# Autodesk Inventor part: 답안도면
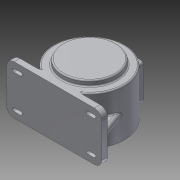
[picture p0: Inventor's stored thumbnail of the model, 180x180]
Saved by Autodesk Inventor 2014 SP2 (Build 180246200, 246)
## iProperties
Created: 2015-06
Part Number: 답안도면
Material: 알루미늄 6061
Document SubType Name: Sheet Metal
Designer: 201-01
Mass: 3440.74 g
Surface Area: 2277.39 cm^2
Volume: 1269.65 cm^3
Density: 2.71 g/cm^3
Sheet Metal Rule: Default_mm
Appearance: 알루미늄 - 평지
Author: 201-01
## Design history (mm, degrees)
sketch "스케치1"
  geometry: L1 (-97, 59)-(97, 59); L2 (115, 41)-(115, -41); L3 (97, -59)-(-97, -59); L4 (-115, -41)-(-115, 41); A1 r 18 centre (97, -41) between (97, -59) and (115, -41); A2 r 18 centre (97, 41) between (115, 41) and (97, 59); A3 r 18 centre (-97, 41) between (-97, 59) and (-115, 41); A4 r 18 centre (-97, -41) between (-115, -41) and (-97, -59); 4 further points
  constraints: 8 end point, 8 point on circle, 8 tangent, 6 point on line, 4 centre point, 3 equal radius, 2 parallel, 1 horizontal, 1 perpendicular
  dimensions: "d0" = 230 distance of point (115, -59) point (-115, -59); "d1" = 118 distance of point (-115, -59) point (-115, 59); "d2" = 115 horizontal distance of point (0, 0) point (-115, 59); "d4" = 59 vertical distance of point (0, 0) point (115, -59); "d5" = 18 radius of A1
extrude "돌출1" join sketch "스케치1" distance "d6" = 14; taper "d7" = 0 deg
sketch "스케치2"
  geometry: L1 (-115, 41)-(-115, -41) reference; L2 (-97, -59)-(97, -59) reference; L3 (115, -41)-(115, 41) reference; L4 (97, 59)-(-97, 59) reference; L5 (0, 59)-(0, 41); L6 (0, 41)-(97, 41); L7 (97, 41)-(81, 41); L8 (81, 50)-(97, 50); L9 (81, 32)-(97, 32); L10 (-115, 0)-(115, 0); L11 (81, -32)-(97, -32); L12 (81, -50)-(97, -50); L13 (-81, 32)-(-97, 32); L14 (-81, 50)-(-97, 50); L15 (-81, -32)-(-97, -32); L16 (-81, -50)-(-97, -50); A1 r 18 centre (-97, -41) between (-115, -41) and (-97, -59) reference; A2 r 18 centre (97, -41) between (97, -59) and (115, -41) reference; A3 r 18 centre (97, 41) between (115, 41) and (97, 59) reference; A4 r 18 centre (-97, 41) between (-97, 59) and (-115, 41) reference; A5 r 9 centre (97, 41) between (97, 32) and (97, 50); A6 r 9 centre (81, 41) between (81, 50) and (81, 32); A7 r 9 centre (97, -41) between (97, -50) and (97, -32); A8 r 9 centre (81, -41) between (81, -32) and (81, -50); A9 r 9 centre (-97, 41) between (-97, 50) and (-97, 32); A10 r 9 centre (-81, 41) between (-81, 32) and (-81, 50); A11 r 9 centre (-97, -41) between (-97, -32) and (-97, -50); A12 r 9 centre (-81, -41) between (-81, -50) and (-81, -32); 2 further points
  constraints: 24 end point, 19 symmetric about line, 16 point on circle, 8 centre point, 3 midpoint, 2 coincident, 2 tangent, 1 parallel, 1 perpendicular, 1 point on line, 6 other
  dimensions: "d9" = 18 distance of L5.start L5.end; "d11" = 16 distance of L6.end L7.end
extrude "돌출2" join sketch "스케치2" distance "d22" = 3; taper "d23" = 0 deg
sketch "스케치3"
  geometry: L1 (-97, 32)-(-81, 32) reference; L2 (-81, 50)-(-97, 50) reference; L3 (-97, 45)-(-81, 45); L4 (-81, 37)-(-97, 37); L5 (0, 0)-(0, 37); L6 (0, 0)-(-32.171, 0); L7 (97, 45)-(81, 45); L8 (81, 37)-(97, 37); L9 (-97, -45)-(-81, -45); L10 (-81, -37)-(-97, -37); L11 (97, -45)-(81, -45); L12 (81, -37)-(97, -37); A1 r 9 centre (-81, 41) between (-81, 32) and (-81, 50) reference; A2 r 9 centre (-97, 41) between (-97, 50) and (-97, 32) reference; A3 r 4 centre (-81, 41) between (-81, 37) and (-81, 45); A4 r 4 centre (-97, 41) between (-97, 45) and (-97, 37); A5 r 4 centre (81, 41) between (81, 45) and (81, 37); A6 r 4 centre (97, 41) between (97, 37) and (97, 45); A7 r 4 centre (-81, -41) between (-81, -45) and (-81, -37); A8 r 4 centre (-97, -41) between (-97, -37) and (-97, -45); A9 r 4 centre (81, -41) between (81, -37) and (81, -45); A10 r 4 centre (97, -41) between (97, -45) and (97, -37)
  constraints: 20 end point, 18 symmetric about line, 16 point on circle, 8 centre point, 2 perpendicular, 9 other
  dimensions: "d24" = 8 distance between parallel lines of L4 L3
extrude "돌출3" cut sketch "스케치3" stored distance "d25" = 3; taper "d26" = 0 deg
fillet "모깎기1" dims "d27" = 4
sketch "스케치5"
  geometry: L1 (0, 0)-(0, 85); C1 r 85 at (0, 85)
  constraints: 2 end point, 1 centre point, 1 coincident, 1 vertical
  dimensions: "d28" = 85 distance of L1.start L1.end; "d29" = 170 diameter of C1
extrude "돌출4" join sketch "스케치5" stored distance "d30" = 118; taper "d31" = 0 deg
sketch "스케치6"
  geometry: L1 (-97, 0)-(97, 0) reference; L2 (97, 0)-(97, 14) reference; L3 (46.733, 14)-(97, 14) reference; L4 (-97, 14)-(-46.733, 14) reference; L5 (-97, 0)-(-97, 14) reference; C1 r 77 at (0, 85); A1 r 85 centre (0, 85) between (46.733, 14) and (-46.733, 14) reference; 1 further point
  constraints: 1 centre point, 1 coincident
  dimensions: "d32" = 154 diameter of C1
extrude "돌출5" cut sketch "스케치6" distance "d33" = 47.5; taper "d34" = 0 deg; dims "d43" = 51, "d44" = 0
sketch "스케치7"
  geometry: L1 (0, 0)-(194, 0) reference; L2 (194, 0)-(194, 14) reference; L3 (143.733, 14)-(194, 14) reference; L4 (0, 14)-(50.267, 14) reference; L5 (0, 0)-(0, 14) reference; C1 r 47.5 at (97, 85); A1 r 85 centre (97, 85) between (143.733, 14) and (50.267, 14) reference; 1 further point
  constraints: 1 centre point, 1 coincident
  dimensions: "d35" = 95 diameter of C1
extrude "돌출6" cut sketch "스케치7" distance "d36" = 11; taper "d37" = 0 deg
fillet "모깎기2" dims "d41" = 3
fillet "모깎기3" dims "d42" = 3
sketch "스케치8"
  geometry: C1 r 74 at (0, 0) reference; C2 r 23.5 at (0, 0); 1 further point
  constraints: 1 centre point, 1 coincident
  dimensions: "d45" = 47 diameter of C2
extrude "돌출7" cut sketch "스케치8" distance "d46" = 14; taper "d47" = 0 deg
sketch "스케치9"
  geometry: L1 (0, 0)-(194, 0) reference; L2 (194, 0)-(194, 14) reference; L3 (143.733, 14)-(194, 14) reference; L4 (0, 14)-(50.267, 14) reference; L5 (0, 0)-(0, 14) reference; C1 r 23.5 at (97, 85) reference; C2 r 65 at (97, 85); A1 r 85 centre (97, 85) between (143.733, 14) and (50.267, 14) reference; 1 further point
  constraints: 1 centre point, 1 coincident
  dimensions: "d48" = 130 diameter of C2
extrude "돌출8" join sketch "스케치9" distance "d49" = 13; taper "d50" = 0 deg
fillet "모깎기4" dims "d51" = 3
sketch "스케치10"
  geometry: C1 r 23.5 at (0, 0) reference; C2 r 15 at (0, 0); 1 further point
  constraints: 1 centre point, 1 coincident
  dimensions: "d52" = 30 diameter of C2
extrude "돌출9" cut sketch "스케치10" distance "d53" = 3; taper "d54" = 0 deg
fillet "모깎기5" dims "d55" = 3
node "작업 평면1"
sketch "스케치13"
  geometry: C1 r 65 at (97, 85); C2 r 47.5 at (97, 85) reference; 1 further point
  constraints: 1 centre point
  dimensions: "d67" = 130 diameter of C1
extrude "돌출12" join sketch "스케치13" distance "d68" = 3; taper "d69" = 0 deg
chamfer "모따기3" distance "d70" = 1; stored, may be unused: second distance "d71" = 2, angle "d72" = 45 deg
fillet "모깎기7" dims "d73" = 3
sketch "스케치14" dims "d74" = 12
  geometry: L1 (97, 0)-(115, 0) reference; L2 (115, 0)-(115, 14) reference; L3 (97, 14)-(115, 14) reference; L4 (97, 0)-(97, 14) reference; L5 (109, 14)-(84.818, 79.44); L6 (97, 14)-(41.024, 14) reference; L7 (115, 14)-(97, 14) reference; L8 (109, 14)-(46.733, 14); A1 r 85 centre (0, 85) between (46.733, 14) and (-46.733, 14) reference; 2 further points
  constraints: 4 end point, 1 coincident, 1 horizontal alignment, 1 point on circle, 1 point on line, 2 other
  node "투영된 루프9"
sketch "스케치15"
  geometry: L1 (-35.5, 42.5)-(35.5, 42.5); L2 (42.5, 35.5)-(42.5, -35.5); L3 (35.5, -42.5)-(-35.5, -42.5); L4 (-42.5, -35.5)-(-42.5, 35.5); A1 r 7 centre (-35.5, 35.5) between (-35.5, 42.5) and (-42.5, 35.5); A2 r 7 centre (-35.5, -35.5) between (-42.5, -35.5) and (-35.5, -42.5); A3 r 7 centre (35.5, -35.5) between (35.5, -42.5) and (42.5, -35.5); A4 r 7 centre (35.5, 35.5) between (42.5, 35.5) and (35.5, 42.5); 4 further points
  constraints: 8 end point, 8 point on circle, 8 tangent, 6 point on line, 4 centre point, 3 equal radius, 2 parallel, 1 horizontal, 1 perpendicular
  dimensions: "d84" = 85 distance of point (-42.5, 42.5) point (42.5, 42.5); "d85" = 85 distance of point (-42.5, -42.5) point (-42.5, 42.5); "d86" = 42.5 horizontal distance of point (-42.5, 42.5) point (0, 0); "d87" = 42.5 horizontal distance of point (0, 0) point (42.5, 42.5); "d88" = 7 radius of A1
extrude "돌출13" join sketch "스케치15" stored distance "d89" = 3; taper "d90" = 0 deg
sketch "스케치16"
  geometry: C1 r 35 at (0, 0); 1 further point
  constraints: 1 centre point, 1 coincident
  dimensions: "d91" = 70 diameter of C1
extrude "돌출14" cut sketch "스케치16" stored distance "d92" = 3; taper "d93" = 0 deg
chamfer "모따기4" distance "d94" = 1; stored, may be unused: second distance "d95" = 2, angle "d96" = 45 deg
fillet "모깎기9" dims "d97" = 3
extrude "돌출15" join sketch "스케치14" stored distance "d98" = 15; taper "d99" = 0 deg
fillet "모깎기10" dims "d100" = 7.5
fillet "모깎기11" dims "d101" = 3
fillet "모깎기12" dims "d102" = 3
hole "구멍1" diameter "d105" = 3.242; stored, may be unused: countersink angle "d109" = 90 deg, drill point angle "d111" = 118 deg; dims "d103" = 10, "d104" = 10, "d106" = 10, "d107" = 4, "d108" = 2, "d110" = 13
hole "구멍2" diameter "d114" = 3.242; stored, may be unused: countersink angle "d118" = 90 deg, drill point angle "d120" = 118 deg; dims "d112" = 10, "d113" = 10, "d115" = 10, "d116" = 4, "d117" = 2, "d119" = 13
hole "구멍3" diameter "d123" = 3.242; stored, may be unused: countersink angle "d127" = 90 deg, drill point angle "d129" = 118 deg; dims "d121" = 10, "d122" = 10, "d124" = 10, "d125" = 4, "d126" = 2, "d128" = 13
hole "구멍4" diameter "d132" = 3.242; stored, may be unused: countersink angle "d136" = 90 deg, drill point angle "d138" = 118 deg; dims "d130" = 10, "d131" = 10, "d133" = 10, "d134" = 4, "d135" = 2, "d137" = 13
sketch "스케치17"
  geometry: L1 (0, 0)-(194, 0) reference; L2 (97, 85)-(174.036, 120.923); A1 r 85 centre (97, 85) between (150.953, 19.318) and (43.047, 19.318) reference; 2 further points
  constraints: 2 end point, 1 coincident, 1 point on circle
  dimensions: "d140" = 25 deg angle of L1 L2
node "작업 평면2"
sketch "스케치18"
  geometry: L1 (-7.329, 19.37)-(-7.329, 98.196); L2 (-7.329, 98.196)-(8.671, 98.196); L3 (8.671, 98.196)-(8.671, 19.37); L4 (8.671, 19.37)-(-7.329, 19.37); L5 (80.996, 0)-(-82, 0) reference; L6 (38.023, 66.5)-(-12.432, 66.5) reference; 2 further points
  constraints: 2 other
feature "엠보싱1" sketch "스케치18" dims "d144" = 0.5, "d145" = 0
chamfer "모따기5" distance "d146" = 1; stored, may be unused: second distance "d147" = 2, angle "d148" = 45 deg
fillet "모깎기13" dims "d149" = 0.3
node "솔리드1"
mirror "대칭1"
node "투영된 루프1"
node "투영된 루프2"
node "투영된 루프3"
node "투영된 루프4"
node "투영된 루프5"
node "투영된 루프6"
node "투영된 루프7"
other parameters: "SeamGap" = 0.01, "d20" = 18, "d21" = 18, "d56" = 173, "d76" = 110 deg
